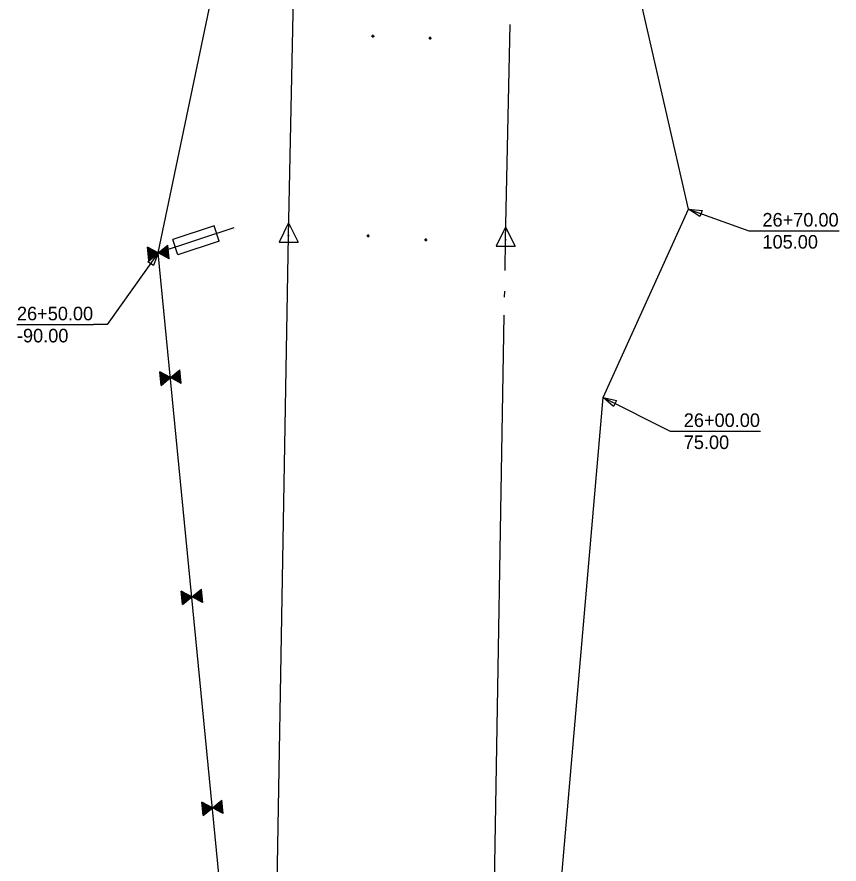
# Model space of a CAD drawing. Extents: x 1443798 to 1476449, y 2041559 to 2057889.
# Drawn here: x 1476095.9 to 1476398.9, y 2055165 to 2055477.1 of the extents above; entities that cross this region are included whole.
import ezdxf

# ---------------------------------------------------------------- set-up
doc = ezdxf.new("R2010")
doc.units = 0
for name, color, linetype in [('Plan Notes', 7, 'Continuous'), ('R_Proposed Fence', 7, 'Continuous'), ('R_ROW', 7, 'Continuous'), ('S_EXIST_ROW', 7, 'Continuous'), ('S_EXIST_ROW_ANNOT', 7, 'Continuous'), ('S_STR_PT_SYM', 7, 'Continuous')]:
    doc.layers.add(name, color=color, linetype=linetype)

msp = doc.modelspace()

# ---------------------------------------------------------------- linework, layer by layer
at = {"layer": 'Plan Notes'}
for p, q in [((1476370.65, 2055398.29), (1476398.88, 2055398.29)), ((1476095.95, 2055363.76), (1476124.18, 2055363.76)), ((1476341.66, 2055324.46), (1476369.89, 2055324.46))]:
    msp.add_line(p, q, dxfattribs=at)
for points in [[(1476343.4, 2055406.29), (1476365.65, 2055398.29), (1476370.65, 2055398.29)], [(1476148.04, 2055390.15), (1476129.18, 2055363.76), (1476124.18, 2055363.76)], [(1476312.02, 2055336.9), (1476336.66, 2055324.46), (1476341.66, 2055324.46)]]:
    msp.add_lwpolyline(points, dxfattribs=at)
for points in [[(1476343.4, 2055406.29), (1476348.38, 2055405.79), (1476347.56, 2055403.51)], [(1476148.04, 2055390.15), (1476146.21, 2055385.5), (1476144.24, 2055386.91)], [(1476312.02, 2055336.9), (1476316.9, 2055335.8), (1476315.81, 2055333.63)]]:
    msp.add_lwpolyline(points, close=True, dxfattribs=at)
at = {"layer": 'R_Proposed Fence'}
for p, q in [((1476175.82, 2055399.36), (1476148.04, 2055390.15)), ((1476168.58, 2055400.12), (1476153.39, 2055395.09)), ((1476170.47, 2055394.42), (1476168.58, 2055400.12)), ((1476155.28, 2055389.39), (1476153.39, 2055395.09)), ((1476170.47, 2055394.42), (1476155.28, 2055389.39)), ((1476148.04, 2055390.15), (1476144.07, 2055392.28)), ((1476147.96, 2055390.11), (1476144.08, 2055392.18)), ((1476147.7, 2055389.96), (1476144.11, 2055391.88)), ((1476147.54, 2055389.76), (1476144.14, 2055391.58)), ((1476147.31, 2055389.6), (1476144.17, 2055391.28)), ((1476147.12, 2055389.42), (1476144.2, 2055390.98)), ((1476148.04, 2055390.15), (1476151.53, 2055393.01)), ((1476148.14, 2055390.12), (1476151.54, 2055392.91)), ((1476148.42, 2055390.03), (1476151.57, 2055392.61)), ((1476148.62, 2055389.87), (1476151.6, 2055392.31)), ((1476148.87, 2055389.75), (1476151.63, 2055392.01)), ((1476149.09, 2055389.61), (1476151.66, 2055391.71)), ((1476149.37, 2055389.52), (1476151.69, 2055391.41)), ((1476149.57, 2055389.36), (1476151.72, 2055391.11)), ((1476146.86, 2055389.27), (1476144.22, 2055390.68)), ((1476146.7, 2055389.08), (1476144.25, 2055390.38)), ((1476146.45, 2055388.93), (1476144.28, 2055390.09)), ((1476146.26, 2055388.75), (1476144.31, 2055389.79)), ((1476145.86, 2055388.39), (1476144.37, 2055389.19)), ((1476145.67, 2055388.21), (1476144.4, 2055388.89)), ((1476145.44, 2055388.05), (1476144.43, 2055388.59)), ((1476145.21, 2055387.89), (1476144.46, 2055388.29)), ((1476145.99, 2055388.6), (1476144.49, 2055389.41)), ((1476145.02, 2055387.71), (1476144.49, 2055387.99)), ((1476144.55, 2055387.3), (1476148.04, 2055390.15)), ((1476152.02, 2055388.03), (1476148.04, 2055390.15)), ((1476149.85, 2055389.26), (1476151.75, 2055390.81)), ((1476150.07, 2055389.12), (1476151.78, 2055390.51)), ((1476150.35, 2055389.03), (1476151.68, 2055390.11)), ((1476150.53, 2055388.85), (1476151.83, 2055389.92)), ((1476150.75, 2055388.71), (1476151.86, 2055389.62)), ((1476151, 2055388.59), (1476151.89, 2055389.32)), ((1476151.26, 2055388.48), (1476151.92, 2055389.02)), ((1476151.48, 2055388.34), (1476151.95, 2055388.72)), ((1476151.74, 2055388.22), (1476151.98, 2055388.42)), ((1476151.96, 2055388.08), (1476152.01, 2055388.12)), ((1476144.79, 2055387.54), (1476144.52, 2055387.69)), ((1476144.6, 2055387.36), (1476144.55, 2055387.39)), ((1476152.53, 2055344.2), (1476148.56, 2055346.33)), ((1476152.44, 2055344.15), (1476148.57, 2055346.23)), ((1476152.19, 2055344.01), (1476148.59, 2055345.93)), ((1476152.02, 2055343.81), (1476148.62, 2055345.63)), ((1476151.79, 2055343.65), (1476148.65, 2055345.33)), ((1476151.6, 2055343.47), (1476148.68, 2055345.03)), ((1476151.35, 2055343.32), (1476148.71, 2055344.73)), ((1476151.18, 2055343.13), (1476148.74, 2055344.43)), ((1476149.04, 2055341.35), (1476152.53, 2055344.2)), ((1476152.53, 2055344.2), (1476156.02, 2055347.05)), ((1476156.51, 2055342.08), (1476152.53, 2055344.2)), ((1476152.63, 2055344.17), (1476156.03, 2055346.95)), ((1476152.9, 2055344.07), (1476156.06, 2055346.66)), ((1476153.1, 2055343.92), (1476156.09, 2055346.36)), ((1476153.36, 2055343.8), (1476156.12, 2055346.06)), ((1476153.58, 2055343.66), (1476156.15, 2055345.76)), ((1476153.86, 2055343.57), (1476156.18, 2055345.46)), ((1476154.06, 2055343.41), (1476156.2, 2055345.16)), ((1476154.33, 2055343.31), (1476156.23, 2055344.86)), ((1476154.56, 2055343.17), (1476156.26, 2055344.56)), ((1476154.84, 2055343.08), (1476156.16, 2055344.16)), ((1476150.93, 2055342.98), (1476148.77, 2055344.13)), ((1476150.74, 2055342.8), (1476148.8, 2055343.83)), ((1476150.35, 2055342.44), (1476148.86, 2055343.24)), ((1476150.15, 2055342.26), (1476148.89, 2055342.94)), ((1476149.93, 2055342.1), (1476148.92, 2055342.64)), ((1476149.7, 2055341.94), (1476148.94, 2055342.34)), ((1476150.48, 2055342.65), (1476148.97, 2055343.46)), ((1476149.51, 2055341.75), (1476148.97, 2055342.04)), ((1476149.28, 2055341.59), (1476149, 2055341.74)), ((1476149.09, 2055341.41), (1476149.03, 2055341.44)), ((1476155.01, 2055342.9), (1476156.32, 2055343.96)), ((1476155.24, 2055342.76), (1476156.35, 2055343.67)), ((1476155.49, 2055342.64), (1476156.38, 2055343.37)), ((1476155.75, 2055342.53), (1476156.41, 2055343.07)), ((1476155.97, 2055342.38), (1476156.44, 2055342.77)), ((1476156.22, 2055342.27), (1476156.47, 2055342.47)), ((1476156.45, 2055342.13), (1476156.5, 2055342.17)), ((1476160.41, 2055263.47), (1476163.9, 2055266.32)), ((1476160.51, 2055263.44), (1476163.91, 2055266.22)), ((1476160.41, 2055263.47), (1476156.44, 2055265.59)), ((1476160.32, 2055263.42), (1476156.45, 2055265.49)), ((1476160.07, 2055263.27), (1476156.48, 2055265.2)), ((1476159.91, 2055263.08), (1476156.51, 2055264.9)), ((1476159.68, 2055262.92), (1476156.54, 2055264.6)), ((1476159.49, 2055262.74), (1476156.56, 2055264.3)), ((1476159.23, 2055262.59), (1476156.59, 2055264)), ((1476159.07, 2055262.39), (1476156.62, 2055263.7)), ((1476158.82, 2055262.25), (1476156.65, 2055263.4)), ((1476158.62, 2055262.06), (1476156.68, 2055263.1)), ((1476156.92, 2055260.62), (1476160.41, 2055263.47)), ((1476164.39, 2055261.35), (1476160.41, 2055263.47)), ((1476160.79, 2055263.34), (1476163.94, 2055265.92)), ((1476160.99, 2055263.19), (1476163.97, 2055265.62)), ((1476161.24, 2055263.07), (1476164, 2055265.33)), ((1476161.46, 2055262.93), (1476164.03, 2055265.03)), ((1476161.74, 2055262.83), (1476164.06, 2055264.73)), ((1476161.94, 2055262.67), (1476164.09, 2055264.43)), ((1476162.22, 2055262.58), (1476164.12, 2055264.13)), ((1476162.44, 2055262.44), (1476164.15, 2055263.83)), ((1476162.72, 2055262.35), (1476164.05, 2055263.43)), ((1476162.9, 2055262.16), (1476164.2, 2055263.23)), ((1476158.23, 2055261.71), (1476156.74, 2055262.5)), ((1476158.04, 2055261.53), (1476156.77, 2055262.21)), ((1476157.81, 2055261.37), (1476156.8, 2055261.91)), ((1476157.58, 2055261.2), (1476156.83, 2055261.61)), ((1476158.36, 2055261.92), (1476156.86, 2055262.72)), ((1476157.39, 2055261.02), (1476156.86, 2055261.31)), ((1476157.16, 2055260.86), (1476156.89, 2055261.01)), ((1476156.97, 2055260.68), (1476156.91, 2055260.71)), ((1476163.12, 2055262.02), (1476164.23, 2055262.93)), ((1476163.37, 2055261.91), (1476164.26, 2055262.64)), ((1476163.63, 2055261.79), (1476164.29, 2055262.34)), ((1476163.85, 2055261.65), (1476164.32, 2055262.04)), ((1476164.11, 2055261.54), (1476164.35, 2055261.74)), ((1476164.33, 2055261.4), (1476164.38, 2055261.44)), ((1476168, 2055185.73), (1476171.49, 2055188.58)), ((1476168.1, 2055185.7), (1476171.5, 2055188.48)), ((1476168.38, 2055185.6), (1476171.53, 2055188.18)), ((1476168, 2055185.73), (1476164.03, 2055187.85)), ((1476167.91, 2055185.68), (1476164.04, 2055187.75)), ((1476167.66, 2055185.53), (1476164.07, 2055187.45)), ((1476167.5, 2055185.34), (1476164.1, 2055187.15)), ((1476167.27, 2055185.18), (1476164.13, 2055186.86)), ((1476167.08, 2055185), (1476164.15, 2055186.56)), ((1476166.82, 2055184.85), (1476164.18, 2055186.26)), ((1476166.66, 2055184.65), (1476164.21, 2055185.96)), ((1476166.41, 2055184.5), (1476164.24, 2055185.66)), ((1476166.21, 2055184.32), (1476164.27, 2055185.36)), ((1476164.51, 2055182.88), (1476168, 2055185.73)), ((1476171.98, 2055183.6), (1476168, 2055185.73)), ((1476168.58, 2055185.44), (1476171.56, 2055187.88)), ((1476168.83, 2055185.33), (1476171.59, 2055187.58)), ((1476169.05, 2055185.19), (1476171.62, 2055187.29)), ((1476169.33, 2055185.09), (1476171.65, 2055186.99)), ((1476169.53, 2055184.93), (1476171.68, 2055186.69)), ((1476169.81, 2055184.84), (1476171.71, 2055186.39)), ((1476170.03, 2055184.69), (1476171.74, 2055186.09)), ((1476170.31, 2055184.6), (1476171.64, 2055185.68)), ((1476170.49, 2055184.42), (1476171.79, 2055185.49)), ((1476170.71, 2055184.28), (1476171.82, 2055185.19)), ((1476165.82, 2055183.97), (1476164.33, 2055184.76)), ((1476165.63, 2055183.79), (1476164.36, 2055184.46)), ((1476165.4, 2055183.62), (1476164.39, 2055184.16)), ((1476165.17, 2055183.46), (1476164.42, 2055183.87)), ((1476165.95, 2055184.18), (1476164.45, 2055184.98)), ((1476164.98, 2055183.28), (1476164.45, 2055183.57)), ((1476164.75, 2055183.12), (1476164.48, 2055183.27)), ((1476164.56, 2055182.94), (1476164.51, 2055182.97)), ((1476170.96, 2055184.17), (1476171.85, 2055184.89)), ((1476171.22, 2055184.05), (1476171.88, 2055184.59)), ((1476171.44, 2055183.91), (1476171.91, 2055184.29)), ((1476171.7, 2055183.8), (1476171.94, 2055184)), ((1476171.92, 2055183.66), (1476171.97, 2055183.7))]:
    msp.add_line(p, q, dxfattribs=at)
for points in [[(1476144.55, 2055387.3), (1476144.07, 2055392.28)], [(1476152.02, 2055388.03), (1476151.53, 2055393.01)], [(1476149.04, 2055341.35), (1476148.56, 2055346.33)], [(1476156.51, 2055342.08), (1476156.02, 2055347.05)], [(1476164.39, 2055261.35), (1476163.9, 2055266.32)], [(1476156.92, 2055260.62), (1476156.44, 2055265.59)], [(1476171.98, 2055183.6), (1476171.49, 2055188.58)], [(1476164.51, 2055182.88), (1476164.03, 2055187.85)]]:
    msp.add_lwpolyline(points, dxfattribs=at)
at = {"layer": 'R_ROW'}
for points in [[(1476186.62, 2054859.81), (1476148.84, 2054931.09), (1476150.62, 2055015.03), (1476181.31, 2055049.43), (1476148.04, 2055390.15), (1476173.45, 2055511.72), (1476163.58, 2055669.9), (1476210, 2056068.52)], [(1476266.59, 2054857.19), (1476319.08, 2054935.51), (1476286.09, 2055037.35), (1476312.02, 2055336.9), (1476343.4, 2055406.29), (1476319.91, 2055508.84), (1476306.57, 2055567.05), (1476338.55, 2055666.44), (1476290.01, 2056067.99)]]:
    msp.add_lwpolyline(points, dxfattribs=at)
at = {"layer": 'S_EXIST_ROW'}
for p, q in [((1476196.03, 2055396.48), (1476234.51, 2057247.25)), ((1476276.01, 2055394.95), (1476277.66, 2055474.31)), ((1476156.76, 2053156.06), (1476196.03, 2055396.48)), ((1476275.82, 2055383.62), (1476276.01, 2055394.95)), ((1476275.64, 2055373.88), (1476275.68, 2055376.01)), ((1476254.56, 2054170.96), (1476275.53, 2055367.16))]:
    msp.add_line(p, q, dxfattribs=at)
at = {"layer": 'S_EXIST_ROW_ANNOT'}
for p, q in [((1476196.04, 2055401.21), (1476192.52, 2055394.12)), ((1476196.04, 2055401.21), (1476199.53, 2055394.12)), ((1476276.03, 2055399.68), (1476272.5, 2055392.59)), ((1476276.03, 2055399.68), (1476279.51, 2055392.59)), ((1476192.52, 2055394.12), (1476199.53, 2055394.12)), ((1476196.03, 2055396.48), (1476196.03, 2055396.48)), ((1476276.01, 2055394.95), (1476276.01, 2055394.95)), ((1476272.5, 2055392.59), (1476279.51, 2055392.59))]:
    msp.add_line(p, q, dxfattribs=at)
for centre, radius in [((1476196.03, 2055396.48), 0.12), ((1476196.03, 2055396.48), 0.06), ((1476276.01, 2055394.95), 0.12), ((1476276.01, 2055394.95), 0.06)]:
    msp.add_circle(centre, radius, dxfattribs=at)
at = {"layer": 'S_STR_PT_SYM'}
for points in [[(1476227.14, 2055470.03), (1476227.14, 2055470.53), (1476227.14, 2055470.03), (1476226.64, 2055470.03), (1476227.14, 2055470.03), (1476227.14, 2055469.53), (1476227.14, 2055470.03), (1476227.64, 2055470.03)], [(1476248.17, 2055469.28), (1476248.17, 2055469.78), (1476248.17, 2055469.28), (1476247.67, 2055469.28), (1476248.17, 2055469.28), (1476248.17, 2055468.78), (1476248.17, 2055469.28), (1476248.67, 2055469.28)], [(1476225.4, 2055396.42), (1476225.4, 2055396.92), (1476225.4, 2055396.42), (1476224.9, 2055396.42), (1476225.4, 2055396.42), (1476225.4, 2055395.92), (1476225.4, 2055396.42), (1476225.9, 2055396.42)], [(1476246.64, 2055395.02), (1476246.64, 2055395.52), (1476246.64, 2055395.02), (1476246.14, 2055395.02), (1476246.64, 2055395.02), (1476246.64, 2055394.52), (1476246.64, 2055395.02), (1476247.14, 2055395.02)]]:
    msp.add_lwpolyline(points, dxfattribs=at)

# ---------------------------------------------------------------- texts
at = {"layer": 'Plan Notes'}
for s, p in [('26+70.00', (1476370.65, 2055399.86)), ('105.00', (1476370.65, 2055391.73)), ('26+50.00', (1476095.95, 2055365.32)), ('-90.00', (1476095.95, 2055357.19)), ('26+00.00', (1476341.66, 2055326.03)), ('75.00', (1476341.66, 2055317.9))]:
    msp.add_text(s, height=5, dxfattribs=at).set_placement(p)

doc.saveas('drawing.dxf')
